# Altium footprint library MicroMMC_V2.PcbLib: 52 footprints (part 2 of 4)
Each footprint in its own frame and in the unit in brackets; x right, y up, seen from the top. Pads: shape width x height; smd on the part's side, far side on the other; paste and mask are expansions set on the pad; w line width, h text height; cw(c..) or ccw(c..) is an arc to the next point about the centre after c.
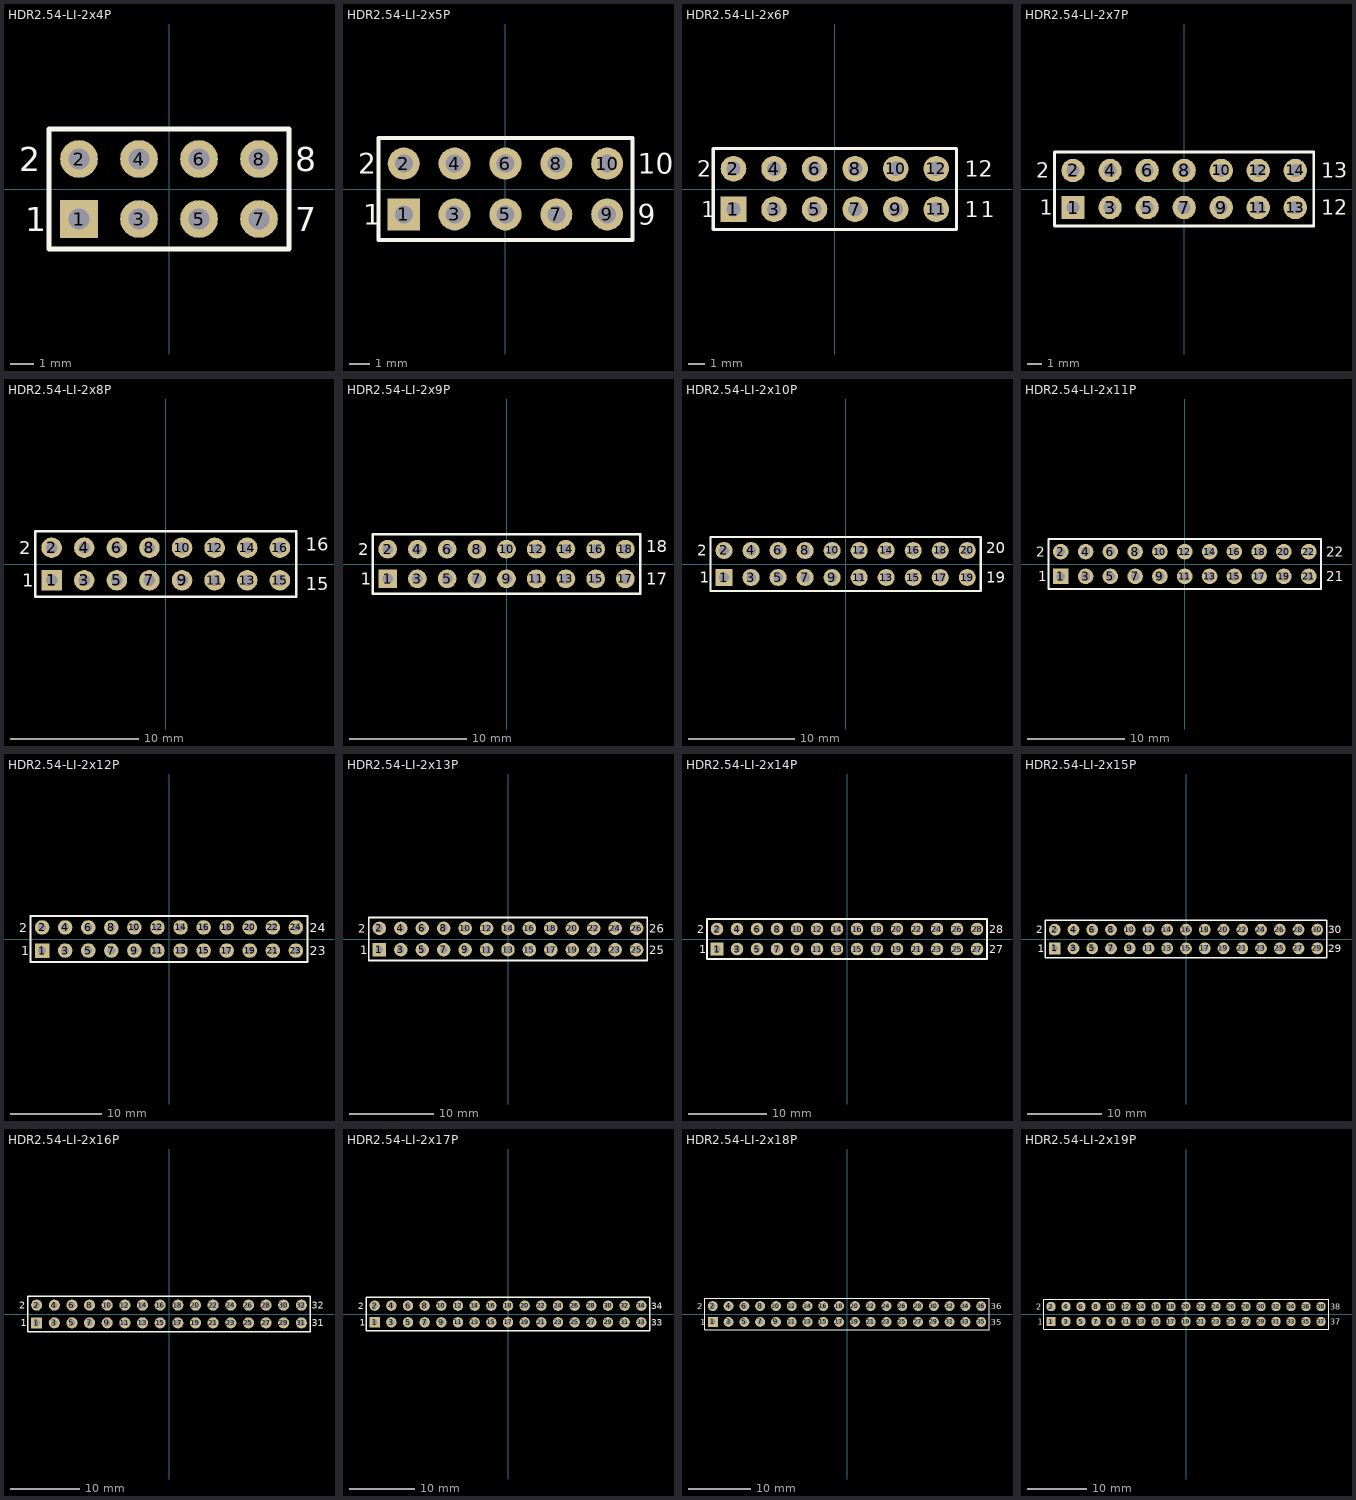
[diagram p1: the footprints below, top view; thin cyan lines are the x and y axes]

## HDR2.54-LI-2x4P [mm] "双排排针，4x2脚"
pads (8):
  rect 1.6x1.6 hole 0.9: 1(-3.81,-1.27)
  round 1.6 hole 0.9: 2(-3.81,1.27) 3(-1.27,-1.27) 4(-1.27,1.27) 5(1.27,-1.27) 6(1.27,1.27) 7(3.81,-1.27) 8(3.81,1.27)
Top Overlay:
  lines w0.2: -2.328,-2.54 5.08,-2.54 5.08,2.54 -5.08,2.54 -5.08,-2.54 2.54,-2.54
  text "8" at 5.334,0.762 h1.02
  text "1" at -6.096,-1.778 h1.02
  text "2" at -6.35,0.762 h1.02
  text "7" at 5.334,-1.778 h1.02
3D body "HDR2.54-1x2P.STEP": height 8.5, standoff -3, extent -2.54,-2.54 0,2.54
3D body "HDR2.54-1x2P.STEP": height 8.5, standoff -3, extent -5.08,-2.54 -2.54,2.54
3D body "HDR2.54-1x2P.STEP": height 8.5, standoff -3, extent 2.54,-2.54 5.08,2.54
3D body "HDR2.54-1x2P.STEP": height 8.5, standoff -3, extent 0,-2.54 2.54,2.54

## HDR2.54-LI-2x5P [mm] "双排排针，5x2脚"
pads (10):
  rect 1.6x1.6 hole 0.9: 1(-5.08,-1.27)
  round 1.6 hole 0.9: 2(-5.08,1.27) 3(-2.54,-1.27) 4(-2.54,1.27) 5(0,-1.27) 6(0,1.27) 7(2.54,-1.27) 8(2.54,1.27) 9(5.08,-1.27) 10(5.08,1.27)
Top Overlay:
  lines w0.2: -6.35,-2.54 6.35,-2.54 6.35,2.54 -6.35,2.54 -6.35,-2.54
  text "10" at 6.604,0.762 h1.02
  text "9" at 6.604,-1.778 h1.02
  text "1" at -7.112,-1.778 h1.02
  text "2" at -7.366,0.762 h1.02
3D body "HDR2.54-1x2P.STEP": height 8.5, standoff -3, extent 3.81,-2.54 6.35,2.54
3D body "HDR2.54-1x2P.STEP": height 8.5, standoff -3, extent -3.81,-2.54 -1.27,2.54
3D body "HDR2.54-1x2P.STEP": height 8.5, standoff -3, extent -6.35,-2.54 -3.81,2.54
3D body "HDR2.54-1x2P.STEP": height 8.5, standoff -3, extent 1.27,-2.54 3.81,2.54
3D body "HDR2.54-1x2P.STEP": height 8.5, standoff -3, extent -1.27,-2.54 1.27,2.54

## HDR2.54-LI-2x6P [mm] "双排排针，6x2脚"
pads (12):
  rect 1.6x1.6 hole 0.9: 1(-6.35,-1.27)
  round 1.6 hole 0.9: 2(-6.35,1.27) 3(-3.81,-1.27) 4(-3.81,1.27) 5(-1.27,-1.27) 6(-1.27,1.27) 7(1.27,-1.27) 8(1.27,1.27) 9(3.81,-1.27) 10(3.81,1.27) 11(6.35,-1.27) 12(6.35,1.27)
Top Overlay:
  lines w0.2: -7.62,-2.54 7.62,-2.54 7.62,2.54 -7.62,2.54 -7.62,-2.54
  text "12" at 8.128,0.762 h1.02
  text "1" at 9.144,-1.778 h1.02
  text "1" at 8.128,-1.778 h1.02
  text "1" at -8.382,-1.778 h1.02
  text "2" at -8.636,0.762 h1.02
3D body "HDR2.54-1x2P.STEP": height 8.5, standoff -3, extent 2.54,-2.54 5.08,2.54
3D body "HDR2.54-1x2P.STEP": height 8.5, standoff -3, extent -5.08,-2.54 -2.54,2.54
3D body "HDR2.54-1x2P.STEP": height 8.5, standoff -3, extent -7.62,-2.54 -5.08,2.54
3D body "HDR2.54-1x2P.STEP": height 8.5, standoff -3, extent 0,-2.54 2.54,2.54
3D body "HDR2.54-1x2P.STEP": height 8.5, standoff -3, extent -2.54,-2.54 0,2.54
3D body "HDR2.54-1x2P.STEP": height 8.5, standoff -3, extent 5.08,-2.54 7.62,2.54

## HDR2.54-LI-2x7P [mm] "双排排针，7x2脚"
pads (14):
  rect 1.6x1.6 hole 0.9: 1(-7.62,-1.27)
  round 1.6 hole 0.9: 2(-7.62,1.27) 3(-5.08,-1.27) 4(-5.08,1.27) 5(-2.54,-1.27) 6(-2.54,1.27) 7(0,-1.27) 8(0,1.27) 9(2.54,-1.27) 10(2.54,1.27) 11(5.08,-1.27) 12(5.08,1.27) 13(7.62,-1.27) 14(7.62,1.27)
Top Overlay:
  lines w0.2: -8.89,-2.54 8.89,-2.54 8.89,2.54 -8.89,2.54 -8.89,-2.54
  text "12" at 9.398,-1.778 h1.02
  text "13" at 9.398,0.762 h1.02
  text "1" at -9.906,-1.778 h1.02
  text "2" at -10.16,0.762 h1.02
3D body "HDR2.54-1x2P.STEP": height 8.5, standoff -3, extent 1.27,-2.54 3.81,2.54
3D body "HDR2.54-1x2P.STEP": height 8.5, standoff -3, extent -6.35,-2.54 -3.81,2.54
3D body "HDR2.54-1x2P.STEP": height 8.5, standoff -3, extent -8.89,-2.54 -6.35,2.54
3D body "HDR2.54-1x2P.STEP": height 8.5, standoff -3, extent -1.27,-2.54 1.27,2.54
3D body "HDR2.54-1x2P.STEP": height 8.5, standoff -3, extent -3.81,-2.54 -1.27,2.54
3D body "HDR2.54-1x2P.STEP": height 8.5, standoff -3, extent 6.35,-2.54 8.89,2.54
3D body "HDR2.54-1x2P.STEP": height 8.5, standoff -3, extent 3.81,-2.54 6.35,2.54

## HDR2.54-LI-2x8P [mm] "双排排针，8x2脚"
pads (16):
  rect 1.6x1.6 hole 0.9: 1(-8.89,-1.27)
  round 1.6 hole 0.9: 2(-8.89,1.27) 3(-6.35,-1.27) 4(-6.35,1.27) 5(-3.81,-1.27) 6(-3.81,1.27) 7(-1.27,-1.27) 8(-1.27,1.27) 9(1.27,-1.27) 10(1.27,1.27) 11(3.81,-1.27) 12(3.81,1.27) 13(6.35,-1.27) 14(6.35,1.27) 15(8.89,-1.27) 16(8.89,1.27)
Top Overlay:
  lines w0.2: -10.16,-2.54 -10.16,2.54 10.16,2.54 10.16,-2.54 -10.16,-2.54
  text "2" at -11.43,0.762 h1.02
  text "1" at -11.176,-1.778 h1.02
  text "16" at 10.922,1.016 h1.02
  text "15" at 10.922,-2.032 h1.02
3D body "HDR2.54-1x2P.STEP": height 8.5, standoff -3, extent 0,-2.54 2.54,2.54
3D body "HDR2.54-1x2P.STEP": height 8.5, standoff -3, extent -7.62,-2.54 -5.08,2.54
3D body "HDR2.54-1x2P.STEP": height 8.5, standoff -3, extent -10.16,-2.54 -7.62,2.54
3D body "HDR2.54-1x2P.STEP": height 8.5, standoff -3, extent -2.54,-2.54 0,2.54
3D body "HDR2.54-1x2P.STEP": height 8.5, standoff -3, extent -5.08,-2.54 -2.54,2.54
3D body "HDR2.54-1x2P.STEP": height 8.5, standoff -3, extent 5.08,-2.54 7.62,2.54
3D body "HDR2.54-1x2P.STEP": height 8.5, standoff -3, extent 2.54,-2.54 5.08,2.54
3D body "HDR2.54-1x2P.STEP": height 8.5, standoff -3, extent 7.62,-2.54 10.16,2.54

## HDR2.54-LI-2x9P [mm] "双排排针，9x2脚"
pads (18):
  rect 1.6x1.6 hole 0.9: 1(-10.16,-1.27)
  round 1.6 hole 0.9: 2(-10.16,1.27) 3(-7.62,-1.27) 4(-7.62,1.27) 5(-5.08,-1.27) 6(-5.08,1.27) 7(-2.54,-1.27) 8(-2.54,1.27) 9(0,-1.27) 10(0,1.27) 11(2.54,-1.27) 12(2.54,1.27) 13(5.08,-1.27) 14(5.08,1.27) 15(7.62,-1.27) 16(7.62,1.27) 17(10.16,-1.27) 18(10.16,1.27)
Top Overlay:
  lines w0.2: -11.43,-2.54 11.43,-2.54 11.43,2.54 -11.43,2.54 -11.43,-2.54
  text "17" at 11.938,-1.778 h1.02
  text "18" at 11.938,1.016 h1.02
  text "1" at -12.446,-1.778 h1.02
  text "2" at -12.7,0.762 h1.02
3D body "HDR2.54-1x2P.STEP": height 8.5, standoff -3, extent 6.35,-2.54 8.89,2.54
3D body "HDR2.54-1x2P.STEP": height 8.5, standoff -3, extent 8.89,-2.54 11.43,2.54
3D body "HDR2.54-1x2P.STEP": height 8.5, standoff -3, extent 1.27,-2.54 3.81,2.54
3D body "HDR2.54-1x2P.STEP": height 8.5, standoff -3, extent 3.81,-2.54 6.35,2.54
3D body "HDR2.54-1x2P.STEP": height 8.5, standoff -3, extent -6.35,-2.54 -3.81,2.54
3D body "HDR2.54-1x2P.STEP": height 8.5, standoff -3, extent -3.81,-2.54 -1.27,2.54
3D body "HDR2.54-1x2P.STEP": height 8.5, standoff -3, extent -11.43,-2.54 -8.89,2.54
3D body "HDR2.54-1x2P.STEP": height 8.5, standoff -3, extent -8.89,-2.54 -6.35,2.54
3D body "HDR2.54-1x2P.STEP": height 8.5, standoff -3, extent -1.27,-2.54 1.27,2.54

## HDR2.54-LI-2x10P [mm] "双排排针，10x2脚"
pads (20):
  rect 1.6x1.6 hole 0.9: 1(-11.43,-1.27)
  round 1.6 hole 0.9: 2(-11.43,1.27) 3(-8.89,-1.27) 4(-8.89,1.27) 5(-6.35,-1.27) 6(-6.35,1.27) 7(-3.81,-1.27) 8(-3.81,1.27) 9(-1.27,-1.27) 10(-1.27,1.27) 11(1.27,-1.27) 12(1.27,1.27) 13(3.81,-1.27) 14(3.81,1.27) 15(6.35,-1.27) 16(6.35,1.27) 17(8.89,-1.27) 18(8.89,1.27) 19(11.43,-1.27) 20(11.43,1.27)
Top Overlay:
  lines w0.2: -12.7,-2.54 -12.7,2.54 12.7,2.54 12.7,-2.54 -12.7,-2.54
  text "2" at -13.97,0.762 h1.02
  text "1" at -13.716,-1.778 h1.02
  text "20" at 13.208,1.016 h1.02
  text "19" at 13.208,-1.778 h1.02
3D body "HDR2.54-1x2P.STEP": height 8.5, standoff -3, extent -2.54,-2.54 0,2.54
3D body "HDR2.54-1x2P.STEP": height 8.5, standoff -3, extent -10.16,-2.54 -7.62,2.54
3D body "HDR2.54-1x2P.STEP": height 8.5, standoff -3, extent -12.7,-2.54 -10.16,2.54
3D body "HDR2.54-1x2P.STEP": height 8.5, standoff -3, extent -5.08,-2.54 -2.54,2.54
3D body "HDR2.54-1x2P.STEP": height 8.5, standoff -3, extent -7.62,-2.54 -5.08,2.54
3D body "HDR2.54-1x2P.STEP": height 8.5, standoff -3, extent 10.16,-2.54 12.7,2.54
3D body "HDR2.54-1x2P.STEP": height 8.5, standoff -3, extent 2.54,-2.54 5.08,2.54
3D body "HDR2.54-1x2P.STEP": height 8.5, standoff -3, extent 0,-2.54 2.54,2.54
3D body "HDR2.54-1x2P.STEP": height 8.5, standoff -3, extent 7.62,-2.54 10.16,2.54
3D body "HDR2.54-1x2P.STEP": height 8.5, standoff -3, extent 5.08,-2.54 7.62,2.54

## HDR2.54-LI-2x11P [mm] "双排排针，11x2脚"
pads (22):
  rect 1.6x1.6 hole 0.9: 1(-12.7,-1.27)
  round 1.6 hole 0.9: 2(-12.7,1.27) 3(-10.16,-1.27) 4(-10.16,1.27) 5(-7.62,-1.27) 6(-7.62,1.27) 7(-5.08,-1.27) 8(-5.08,1.27) 9(-2.54,-1.27) 10(-2.54,1.27) 11(0,-1.27) 12(0,1.27) 13(2.54,-1.27) 14(2.54,1.27) 15(5.08,-1.27) 16(5.08,1.27) 17(7.62,-1.27) 18(7.62,1.27) 19(10.16,-1.27) 20(10.16,1.27) 21(12.7,-1.27) 22(12.7,1.27)
Top Overlay:
  lines w0.2: -13.97,-2.54 13.97,-2.54 13.97,2.54 -13.97,2.54 -13.97,-2.54
  text "22" at 14.478,0.762 h1.02
  text "21" at 14.478,-1.778 h1.02
  text "2" at -15.24,0.762 h1.02
  text "1" at -14.986,-1.778 h1.02
3D body "HDR2.54-1x2P.STEP": height 8.5, standoff -3, extent 11.43,-2.54 13.97,2.54
3D body "HDR2.54-1x2P.STEP": height 8.5, standoff -3, extent 3.81,-2.54 6.35,2.54
3D body "HDR2.54-1x2P.STEP": height 8.5, standoff -3, extent 6.35,-2.54 8.89,2.54
3D body "HDR2.54-1x2P.STEP": height 8.5, standoff -3, extent -1.27,-2.54 1.27,2.54
3D body "HDR2.54-1x2P.STEP": height 8.5, standoff -3, extent 1.27,-2.54 3.81,2.54
3D body "HDR2.54-1x2P.STEP": height 8.5, standoff -3, extent 8.89,-2.54 11.43,2.54
3D body "HDR2.54-1x2P.STEP": height 8.5, standoff -3, extent -8.89,-2.54 -6.35,2.54
3D body "HDR2.54-1x2P.STEP": height 8.5, standoff -3, extent -6.35,-2.54 -3.81,2.54
3D body "HDR2.54-1x2P.STEP": height 8.5, standoff -3, extent -13.97,-2.54 -11.43,2.54
3D body "HDR2.54-1x2P.STEP": height 8.5, standoff -3, extent -11.43,-2.54 -8.89,2.54
3D body "HDR2.54-1x2P.STEP": height 8.5, standoff -3, extent -3.81,-2.54 -1.27,2.54

## HDR2.54-LI-2x12P [mm] "双排排针，12x2脚"
pads (24):
  rect 1.6x1.6 hole 0.9: 1(-13.97,-1.27)
  round 1.6 hole 0.9: 2(-13.97,1.27) 3(-11.43,-1.27) 4(-11.43,1.27) 5(-8.89,-1.27) 6(-8.89,1.27) 7(-6.35,-1.27) 8(-6.35,1.27) 9(-3.81,-1.27) 10(-3.81,1.27) 11(-1.27,-1.27) 12(-1.27,1.27) 13(1.27,-1.27) 14(1.27,1.27) 15(3.81,-1.27) 16(3.81,1.27) 17(6.35,-1.27) 18(6.35,1.27) 19(8.89,-1.27) 20(8.89,1.27) 21(11.43,-1.27) 22(11.43,1.27) 23(13.97,-1.27) 24(13.97,1.27)
Top Overlay:
  lines w0.2: -15.24,-2.54 -15.24,2.54 15.24,2.54 15.24,-2.54 -15.24,-2.54
  text "1" at -16.256,-1.778 h1.02
  text "2" at -16.51,0.762 h1.02
  text "23" at 15.494,-1.778 h1.02
  text "24" at 15.494,0.762 h1.02
3D body "HDR2.54-1x2P.STEP": height 8.5, standoff -3, extent -5.08,-2.54 -2.54,2.54
3D body "HDR2.54-1x2P.STEP": height 8.5, standoff -3, extent -12.7,-2.54 -10.16,2.54
3D body "HDR2.54-1x2P.STEP": height 8.5, standoff -3, extent -15.24,-2.54 -12.7,2.54
3D body "HDR2.54-1x2P.STEP": height 8.5, standoff -3, extent -7.62,-2.54 -5.08,2.54
3D body "HDR2.54-1x2P.STEP": height 8.5, standoff -3, extent -10.16,-2.54 -7.62,2.54
3D body "HDR2.54-1x2P.STEP": height 8.5, standoff -3, extent 7.62,-2.54 10.16,2.54
3D body "HDR2.54-1x2P.STEP": height 8.5, standoff -3, extent 0,-2.54 2.54,2.54
3D body "HDR2.54-1x2P.STEP": height 8.5, standoff -3, extent -2.54,-2.54 0,2.54
3D body "HDR2.54-1x2P.STEP": height 8.5, standoff -3, extent 5.08,-2.54 7.62,2.54
3D body "HDR2.54-1x2P.STEP": height 8.5, standoff -3, extent 2.54,-2.54 5.08,2.54
3D body "HDR2.54-1x2P.STEP": height 8.5, standoff -3, extent 12.7,-2.54 15.24,2.54
3D body "HDR2.54-1x2P.STEP": height 8.5, standoff -3, extent 10.16,-2.54 12.7,2.54

## HDR2.54-LI-2x13P [mm] "双排排针，13x2脚"
pads (26):
  rect 1.6x1.6 hole 0.9: 1(-15.24,-1.27)
  round 1.6 hole 0.9: 2(-15.24,1.27) 3(-12.7,-1.27) 4(-12.7,1.27) 5(-10.16,-1.27) 6(-10.16,1.27) 7(-7.62,-1.27) 8(-7.62,1.27) 9(-5.08,-1.27) 10(-5.08,1.27) 11(-2.54,-1.27) 12(-2.54,1.27) 13(0,-1.27) 14(0,1.27) 15(2.54,-1.27) 16(2.54,1.27) 17(5.08,-1.27) 18(5.08,1.27) 19(7.62,-1.27) 20(7.62,1.27) 21(10.16,-1.27) 22(10.16,1.27) 23(12.7,-1.27) 24(12.7,1.27) 25(15.24,-1.27) 26(15.24,1.27)
Top Overlay:
  lines w0.2: -16.51,-2.54 16.51,-2.54 16.51,2.54 -16.51,2.54 -16.51,-2.54
  text "26" at 16.764,0.762 h1.02
  text "25" at 16.764,-1.778 h1.02
  text "1" at -17.526,-1.778 h1.02
  text "2" at -17.78,0.762 h1.02
3D body "HDR2.54-1x2P.STEP": height 8.5, standoff -3, extent 13.97,-2.54 16.51,2.54
3D body "HDR2.54-1x2P.STEP": height 8.5, standoff -3, extent 8.89,-2.54 11.43,2.54
3D body "HDR2.54-1x2P.STEP": height 8.5, standoff -3, extent 11.43,-2.54 13.97,2.54
3D body "HDR2.54-1x2P.STEP": height 8.5, standoff -3, extent 1.27,-2.54 3.81,2.54
3D body "HDR2.54-1x2P.STEP": height 8.5, standoff -3, extent 3.81,-2.54 6.35,2.54
3D body "HDR2.54-1x2P.STEP": height 8.5, standoff -3, extent -3.81,-2.54 -1.27,2.54
3D body "HDR2.54-1x2P.STEP": height 8.5, standoff -3, extent -1.27,-2.54 1.27,2.54
3D body "HDR2.54-1x2P.STEP": height 8.5, standoff -3, extent 6.35,-2.54 8.89,2.54
3D body "HDR2.54-1x2P.STEP": height 8.5, standoff -3, extent -11.43,-2.54 -8.89,2.54
3D body "HDR2.54-1x2P.STEP": height 8.5, standoff -3, extent -8.89,-2.54 -6.35,2.54
3D body "HDR2.54-1x2P.STEP": height 8.5, standoff -3, extent -16.51,-2.54 -13.97,2.54
3D body "HDR2.54-1x2P.STEP": height 8.5, standoff -3, extent -13.97,-2.54 -11.43,2.54
3D body "HDR2.54-1x2P.STEP": height 8.5, standoff -3, extent -6.35,-2.54 -3.81,2.54

## HDR2.54-LI-2x14P [mm] "双排排针，14x2脚"
pads (28):
  rect 1.6x1.6 hole 0.9: 1(-16.51,-1.27)
  round 1.6 hole 0.9: 2(-16.51,1.27) 3(-13.97,-1.27) 4(-13.97,1.27) 5(-11.43,-1.27) 6(-11.43,1.27) 7(-8.89,-1.27) 8(-8.89,1.27) 9(-6.35,-1.27) 10(-6.35,1.27) 11(-3.81,-1.27) 12(-3.81,1.27) 13(-1.27,-1.27) 14(-1.27,1.27) 15(1.27,-1.27) 16(1.27,1.27) 17(3.81,-1.27) 18(3.81,1.27) 19(6.35,-1.27) 20(6.35,1.27) 21(8.89,-1.27) 22(8.89,1.27) 23(11.43,-1.27) 24(11.43,1.27) 25(13.97,-1.27) 26(13.97,1.27) 27(16.51,-1.27) 28(16.51,1.27)
Top Overlay:
  lines w0.2: -17.78,-2.54 17.78,-2.54 17.78,2.54 -17.78,2.54 -17.78,-2.54
  text "28" at 18.034,0.762 h1.02
  text "27" at 18.034,-1.778 h1.02
  text "1" at -18.796,-1.778 h1.02
  text "2" at -19.05,0.762 h1.02
3D body "HDR2.54-1x2P.STEP": height 8.5, standoff -3, extent 12.7,-2.54 15.24,2.54
3D body "HDR2.54-1x2P.STEP": height 8.5, standoff -3, extent 15.24,-2.54 17.78,2.54
3D body "HDR2.54-1x2P.STEP": height 8.5, standoff -3, extent 7.62,-2.54 10.16,2.54
3D body "HDR2.54-1x2P.STEP": height 8.5, standoff -3, extent 10.16,-2.54 12.7,2.54
3D body "HDR2.54-1x2P.STEP": height 8.5, standoff -3, extent 0,-2.54 2.54,2.54
3D body "HDR2.54-1x2P.STEP": height 8.5, standoff -3, extent 2.54,-2.54 5.08,2.54
3D body "HDR2.54-1x2P.STEP": height 8.5, standoff -3, extent -5.08,-2.54 -2.54,2.54
3D body "HDR2.54-1x2P.STEP": height 8.5, standoff -3, extent -2.54,-2.54 0,2.54
3D body "HDR2.54-1x2P.STEP": height 8.5, standoff -3, extent 5.08,-2.54 7.62,2.54
3D body "HDR2.54-1x2P.STEP": height 8.5, standoff -3, extent -12.7,-2.54 -10.16,2.54
3D body "HDR2.54-1x2P.STEP": height 8.5, standoff -3, extent -10.16,-2.54 -7.62,2.54
3D body "HDR2.54-1x2P.STEP": height 8.5, standoff -3, extent -17.78,-2.54 -15.24,2.54
3D body "HDR2.54-1x2P.STEP": height 8.5, standoff -3, extent -15.24,-2.54 -12.7,2.54
3D body "HDR2.54-1x2P.STEP": height 8.5, standoff -3, extent -7.62,-2.54 -5.08,2.54

## HDR2.54-LI-2x15P [mm] "双排排针，15x2脚"
pads (30):
  rect 1.6x1.6 hole 0.9: 1(-17.78,-1.27)
  round 1.6 hole 0.9: 2(-17.78,1.27) 3(-15.24,-1.27) 4(-15.24,1.27) 5(-12.7,-1.27) 6(-12.7,1.27) 7(-10.16,-1.27) 8(-10.16,1.27) 9(-7.62,-1.27) 10(-7.62,1.27) 11(-5.08,-1.27) 12(-5.08,1.27) 13(-2.54,-1.27) 14(-2.54,1.27) 15(0,-1.27) 16(0,1.27) 17(2.54,-1.27) 18(2.54,1.27) 19(5.08,-1.27) 20(5.08,1.27) 21(7.62,-1.27) 22(7.62,1.27) 23(10.16,-1.27) 24(10.16,1.27) 25(12.7,-1.27) 26(12.7,1.27) 27(15.24,-1.27) 28(15.24,1.27) 29(17.78,-1.27) 30(17.78,1.27)
Top Overlay:
  lines w0.2: -19.05,-2.54 -19.05,2.54 19.05,2.54 19.05,-2.54 -19.05,-2.54
  text "30" at 19.304,0.762 h1.02
  text "29" at 19.304,-1.778 h1.02
  text "2" at -20.32,0.762 h1.02
  text "1" at -20.066,-1.778 h1.02
3D body "HDR2.54-1x2P.STEP": height 8.5, standoff -3, extent 11.43,-2.54 13.97,2.54
3D body "HDR2.54-1x2P.STEP": height 8.5, standoff -3, extent 13.97,-2.54 16.51,2.54
3D body "HDR2.54-1x2P.STEP": height 8.5, standoff -3, extent 6.35,-2.54 8.89,2.54
3D body "HDR2.54-1x2P.STEP": height 8.5, standoff -3, extent 8.89,-2.54 11.43,2.54
3D body "HDR2.54-1x2P.STEP": height 8.5, standoff -3, extent 16.51,-2.54 19.05,2.54
3D body "HDR2.54-1x2P.STEP": height 8.5, standoff -3, extent -1.27,-2.54 1.27,2.54
3D body "HDR2.54-1x2P.STEP": height 8.5, standoff -3, extent 1.27,-2.54 3.81,2.54
3D body "HDR2.54-1x2P.STEP": height 8.5, standoff -3, extent -6.35,-2.54 -3.81,2.54
3D body "HDR2.54-1x2P.STEP": height 8.5, standoff -3, extent -3.81,-2.54 -1.27,2.54
3D body "HDR2.54-1x2P.STEP": height 8.5, standoff -3, extent 3.81,-2.54 6.35,2.54
3D body "HDR2.54-1x2P.STEP": height 8.5, standoff -3, extent -13.97,-2.54 -11.43,2.54
3D body "HDR2.54-1x2P.STEP": height 8.5, standoff -3, extent -11.43,-2.54 -8.89,2.54
3D body "HDR2.54-1x2P.STEP": height 8.5, standoff -3, extent -19.05,-2.54 -16.51,2.54
3D body "HDR2.54-1x2P.STEP": height 8.5, standoff -3, extent -16.51,-2.54 -13.97,2.54
3D body "HDR2.54-1x2P.STEP": height 8.5, standoff -3, extent -8.89,-2.54 -6.35,2.54

## HDR2.54-LI-2x16P [mm] "双排排针，16x2脚"
pads (32):
  rect 1.6x1.6 hole 0.9: 1(-19.05,-1.27)
  round 1.6 hole 0.9: 2(-19.05,1.27) 3(-16.51,-1.27) 4(-16.51,1.27) 5(-13.97,-1.27) 6(-13.97,1.27) 7(-11.43,-1.27) 8(-11.43,1.27) 9(-8.89,-1.27) 10(-8.89,1.27) 11(-6.35,-1.27) 12(-6.35,1.27) 13(-3.81,-1.27) 14(-3.81,1.27) 15(-1.27,-1.27) 16(-1.27,1.27) 17(1.27,-1.27) 18(1.27,1.27) 19(3.81,-1.27) 20(3.81,1.27) 21(6.35,-1.27) 22(6.35,1.27) 23(8.89,-1.27) 24(8.89,1.27) 25(11.43,-1.27) 26(11.43,1.27) 27(13.97,-1.27) 28(13.97,1.27) 29(16.51,-1.27) 30(16.51,1.27) 31(19.05,-1.27) 32(19.05,1.27)
Top Overlay:
  lines w0.2: -20.32,-2.54 -20.32,2.54 20.32,2.54 20.32,-2.54 -20.32,-2.54
  text "32" at 20.574,0.762 h1.02
  text "31" at 20.574,-1.778 h1.02
  text "1" at -21.336,-1.778 h1.02
  text "2" at -21.59,0.762 h1.02
3D body "HDR2.54-1x2P.STEP": height 8.5, standoff -3, extent 17.78,-2.54 20.32,2.54
3D body "HDR2.54-1x2P.STEP": height 8.5, standoff -3, extent 10.16,-2.54 12.7,2.54
3D body "HDR2.54-1x2P.STEP": height 8.5, standoff -3, extent 12.7,-2.54 15.24,2.54
3D body "HDR2.54-1x2P.STEP": height 8.5, standoff -3, extent 5.08,-2.54 7.62,2.54
3D body "HDR2.54-1x2P.STEP": height 8.5, standoff -3, extent 7.62,-2.54 10.16,2.54
3D body "HDR2.54-1x2P.STEP": height 8.5, standoff -3, extent 15.24,-2.54 17.78,2.54
3D body "HDR2.54-1x2P.STEP": height 8.5, standoff -3, extent -2.54,-2.54 0,2.54
3D body "HDR2.54-1x2P.STEP": height 8.5, standoff -3, extent 0,-2.54 2.54,2.54
3D body "HDR2.54-1x2P.STEP": height 8.5, standoff -3, extent -7.62,-2.54 -5.08,2.54
3D body "HDR2.54-1x2P.STEP": height 8.5, standoff -3, extent -5.08,-2.54 -2.54,2.54
3D body "HDR2.54-1x2P.STEP": height 8.5, standoff -3, extent 2.54,-2.54 5.08,2.54
3D body "HDR2.54-1x2P.STEP": height 8.5, standoff -3, extent -15.24,-2.54 -12.7,2.54
3D body "HDR2.54-1x2P.STEP": height 8.5, standoff -3, extent -12.7,-2.54 -10.16,2.54
3D body "HDR2.54-1x2P.STEP": height 8.5, standoff -3, extent -20.32,-2.54 -17.78,2.54
3D body "HDR2.54-1x2P.STEP": height 8.5, standoff -3, extent -17.78,-2.54 -15.24,2.54
3D body "HDR2.54-1x2P.STEP": height 8.5, standoff -3, extent -10.16,-2.54 -7.62,2.54

## HDR2.54-LI-2x17P [mm] "双排排针，17x2脚"
pads (34):
  rect 1.6x1.6 hole 0.9: 1(-20.32,-1.27)
  round 1.6 hole 0.9: 2(-20.32,1.27) 3(-17.78,-1.27) 4(-17.78,1.27) 5(-15.24,-1.27) 6(-15.24,1.27) 7(-12.7,-1.27) 8(-12.7,1.27) 9(-10.16,-1.27) 10(-10.16,1.27) 11(-7.62,-1.27) 12(-7.62,1.27) 13(-5.08,-1.27) 14(-5.08,1.27) 15(-2.54,-1.27) 16(-2.54,1.27) 17(0,-1.27) 18(0,1.27) 19(2.54,-1.27) 20(2.54,1.27) 21(5.08,-1.27) 22(5.08,1.27) 23(7.62,-1.27) 24(7.62,1.27) 25(10.16,-1.27) 26(10.16,1.27) 27(12.7,-1.27) 28(12.7,1.27) 29(15.24,-1.27) 30(15.24,1.27) 31(17.78,-1.27) 32(17.78,1.27) 33(20.32,-1.27) 34(20.32,1.27)
Top Overlay:
  lines w0.2: -21.59,-2.54 21.59,-2.54 21.59,2.54 -21.59,2.54 -21.59,-2.54
  text "34" at 21.844,0.762 h1.02
  text "33" at 21.844,-1.778 h1.02
  text "1" at -22.606,-1.778 h1.02
  text "2" at -22.86,0.762 h1.02
3D body "HDR2.54-1x2P.STEP": height 8.5, standoff -3, extent -11.43,-2.54 -8.89,2.54
3D body "HDR2.54-1x2P.STEP": height 8.5, standoff -3, extent -19.05,-2.54 -16.51,2.54
3D body "HDR2.54-1x2P.STEP": height 8.5, standoff -3, extent -21.59,-2.54 -19.05,2.54
3D body "HDR2.54-1x2P.STEP": height 8.5, standoff -3, extent -13.97,-2.54 -11.43,2.54
3D body "HDR2.54-1x2P.STEP": height 8.5, standoff -3, extent -16.51,-2.54 -13.97,2.54
3D body "HDR2.54-1x2P.STEP": height 8.5, standoff -3, extent 1.27,-2.54 3.81,2.54
3D body "HDR2.54-1x2P.STEP": height 8.5, standoff -3, extent -6.35,-2.54 -3.81,2.54
3D body "HDR2.54-1x2P.STEP": height 8.5, standoff -3, extent -8.89,-2.54 -6.35,2.54
3D body "HDR2.54-1x2P.STEP": height 8.5, standoff -3, extent -1.27,-2.54 1.27,2.54
3D body "HDR2.54-1x2P.STEP": height 8.5, standoff -3, extent -3.81,-2.54 -1.27,2.54
3D body "HDR2.54-1x2P.STEP": height 8.5, standoff -3, extent 13.97,-2.54 16.51,2.54
3D body "HDR2.54-1x2P.STEP": height 8.5, standoff -3, extent 6.35,-2.54 8.89,2.54
3D body "HDR2.54-1x2P.STEP": height 8.5, standoff -3, extent 3.81,-2.54 6.35,2.54
3D body "HDR2.54-1x2P.STEP": height 8.5, standoff -3, extent 11.43,-2.54 13.97,2.54
3D body "HDR2.54-1x2P.STEP": height 8.5, standoff -3, extent 8.89,-2.54 11.43,2.54
3D body "HDR2.54-1x2P.STEP": height 8.5, standoff -3, extent 19.05,-2.54 21.59,2.54
3D body "HDR2.54-1x2P.STEP": height 8.5, standoff -3, extent 16.51,-2.54 19.05,2.54

## HDR2.54-LI-2x18P [mm] "双排排针，18x2脚"
pads (36):
  rect 1.6x1.6 hole 0.9: 1(-21.59,-1.27)
  round 1.6 hole 0.9: 2(-21.59,1.27) 3(-19.05,-1.27) 4(-19.05,1.27) 5(-16.51,-1.27) 6(-16.51,1.27) 7(-13.97,-1.27) 8(-13.97,1.27) 9(-11.43,-1.27) 10(-11.43,1.27) 11(-8.89,-1.27) 12(-8.89,1.27) 13(-6.35,-1.27) 14(-6.35,1.27) 15(-3.81,-1.27) 16(-3.81,1.27) 17(-1.27,-1.27) 18(-1.27,1.27) 19(1.27,-1.27) 20(1.27,1.27) 21(3.81,-1.27) 22(3.81,1.27) 23(6.35,-1.27) 24(6.35,1.27) 25(8.89,-1.27) 26(8.89,1.27) 27(11.43,-1.27) 28(11.43,1.27) 29(13.97,-1.27) 30(13.97,1.27) 31(16.51,-1.27) 32(16.51,1.27) 33(19.05,-1.27) 34(19.05,1.27) 35(21.59,-1.27) 36(21.59,1.27)
Top Overlay:
  lines w0.2: -17.78,-2.54 -22.86,-2.54 ; -22.86,-2.54 22.86,-2.54 22.86,2.54 -22.86,2.54 -22.86,-2.54
  text "36" at 23.114,0.762 h1.02
  text "35" at 23.114,-1.778 h1.02
  text "1" at -23.622,-1.778 h1.02
  text "2" at -24.13,0.762 h1.02
3D body "HDR2.54-1x2P.STEP": height 8.5, standoff -3, extent -12.7,-2.54 -10.16,2.54
3D body "HDR2.54-1x2P.STEP": height 8.5, standoff -3, extent -20.32,-2.54 -17.78,2.54
3D body "HDR2.54-1x2P.STEP": height 8.5, standoff -3, extent -22.86,-2.54 -20.32,2.54
3D body "HDR2.54-1x2P.STEP": height 8.5, standoff -3, extent -15.24,-2.54 -12.7,2.54
3D body "HDR2.54-1x2P.STEP": height 8.5, standoff -3, extent -17.78,-2.54 -15.24,2.54
3D body "HDR2.54-1x2P.STEP": height 8.5, standoff -3, extent 0,-2.54 2.54,2.54
3D body "HDR2.54-1x2P.STEP": height 8.5, standoff -3, extent -7.62,-2.54 -5.08,2.54
3D body "HDR2.54-1x2P.STEP": height 8.5, standoff -3, extent -10.16,-2.54 -7.62,2.54
3D body "HDR2.54-1x2P.STEP": height 8.5, standoff -3, extent -2.54,-2.54 0,2.54
3D body "HDR2.54-1x2P.STEP": height 8.5, standoff -3, extent -5.08,-2.54 -2.54,2.54
3D body "HDR2.54-1x2P.STEP": height 8.5, standoff -3, extent 12.7,-2.54 15.24,2.54
3D body "HDR2.54-1x2P.STEP": height 8.5, standoff -3, extent 5.08,-2.54 7.62,2.54
3D body "HDR2.54-1x2P.STEP": height 8.5, standoff -3, extent 2.54,-2.54 5.08,2.54
3D body "HDR2.54-1x2P.STEP": height 8.5, standoff -3, extent 10.16,-2.54 12.7,2.54
3D body "HDR2.54-1x2P.STEP": height 8.5, standoff -3, extent 7.62,-2.54 10.16,2.54
3D body "HDR2.54-1x2P.STEP": height 8.5, standoff -3, extent 17.78,-2.54 20.32,2.54
3D body "HDR2.54-1x2P.STEP": height 8.5, standoff -3, extent 15.24,-2.54 17.78,2.54
3D body "HDR2.54-1x2P.STEP": height 8.5, standoff -3, extent 20.32,-2.54 22.86,2.54

## HDR2.54-LI-2x19P [mm] "双排排针，19x2脚"
pads (38):
  rect 1.6x1.6 hole 0.9: 1(-22.86,-1.27)
  round 1.6 hole 0.9: 2(-22.86,1.27) 3(-20.32,-1.27) 4(-20.32,1.27) 5(-17.78,-1.27) 6(-17.78,1.27) 7(-15.24,-1.27) 8(-15.24,1.27) 9(-12.7,-1.27) 10(-12.7,1.27) 11(-10.16,-1.27) 12(-10.16,1.27) 13(-7.62,-1.27) 14(-7.62,1.27) 15(-5.08,-1.27) 16(-5.08,1.27) 17(-2.54,-1.27) 18(-2.54,1.27) 19(0,-1.27) 20(0,1.27) 21(2.54,-1.27) 22(2.54,1.27) 23(5.08,-1.27) 24(5.08,1.27) 25(7.62,-1.27) 26(7.62,1.27) 27(10.16,-1.27) 28(10.16,1.27) 29(12.7,-1.27) 30(12.7,1.27) 31(15.24,-1.27) 32(15.24,1.27) 33(17.78,-1.27) 34(17.78,1.27) 35(20.32,-1.27) 36(20.32,1.27) 37(22.86,-1.27) 38(22.86,1.27)
Top Overlay:
  lines w0.2: -24.13,-2.54 24.13,-2.54 24.13,2.54 -24.13,2.54 -24.13,-2.54
  text "2" at -25.4,0.762 h1.02
  text "1" at -25.146,-1.778 h1.02
  text "37" at 24.384,-1.778 h1.02
  text "38" at 24.384,0.762 h1.02
3D body "HDR2.54-1x2P.STEP": height 8.5, standoff -3, extent 19.05,-2.54 21.59,2.54
3D body "HDR2.54-1x2P.STEP": height 8.5, standoff -3, extent 21.59,-2.54 24.13,2.54
3D body "HDR2.54-1x2P.STEP": height 8.5, standoff -3, extent 13.97,-2.54 16.51,2.54
3D body "HDR2.54-1x2P.STEP": height 8.5, standoff -3, extent 16.51,-2.54 19.05,2.54
3D body "HDR2.54-1x2P.STEP": height 8.5, standoff -3, extent 6.35,-2.54 8.89,2.54
3D body "HDR2.54-1x2P.STEP": height 8.5, standoff -3, extent 8.89,-2.54 11.43,2.54
3D body "HDR2.54-1x2P.STEP": height 8.5, standoff -3, extent 1.27,-2.54 3.81,2.54
3D body "HDR2.54-1x2P.STEP": height 8.5, standoff -3, extent 3.81,-2.54 6.35,2.54
3D body "HDR2.54-1x2P.STEP": height 8.5, standoff -3, extent 11.43,-2.54 13.97,2.54
3D body "HDR2.54-1x2P.STEP": height 8.5, standoff -3, extent -6.35,-2.54 -3.81,2.54
3D body "HDR2.54-1x2P.STEP": height 8.5, standoff -3, extent -3.81,-2.54 -1.27,2.54
3D body "HDR2.54-1x2P.STEP": height 8.5, standoff -3, extent -11.43,-2.54 -8.89,2.54
3D body "HDR2.54-1x2P.STEP": height 8.5, standoff -3, extent -8.89,-2.54 -6.35,2.54
3D body "HDR2.54-1x2P.STEP": height 8.5, standoff -3, extent -1.27,-2.54 1.27,2.54
3D body "HDR2.54-1x2P.STEP": height 8.5, standoff -3, extent -19.05,-2.54 -16.51,2.54
3D body "HDR2.54-1x2P.STEP": height 8.5, standoff -3, extent -16.51,-2.54 -13.97,2.54
3D body "HDR2.54-1x2P.STEP": height 8.5, standoff -3, extent -24.13,-2.54 -21.59,2.54
3D body "HDR2.54-1x2P.STEP": height 8.5, standoff -3, extent -21.59,-2.54 -19.05,2.54
3D body "HDR2.54-1x2P.STEP": height 8.5, standoff -3, extent -13.97,-2.54 -11.43,2.54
